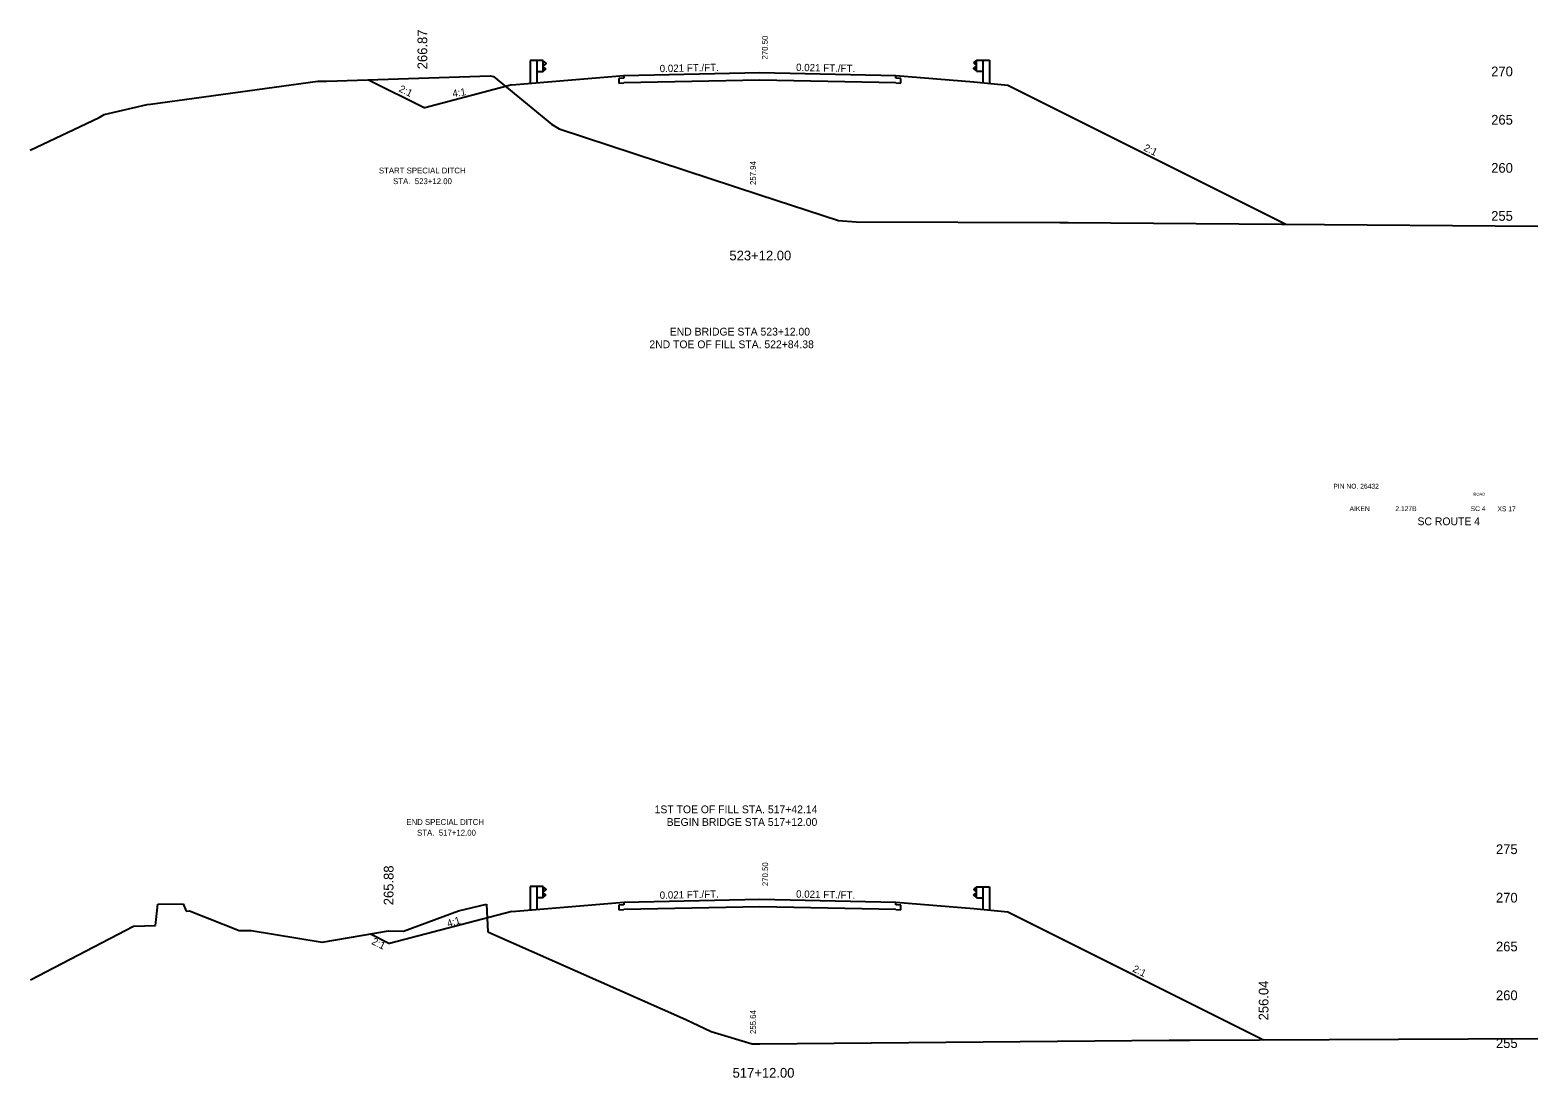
# Model space of a CAD drawing. Extents: x 883 to 1160, y 1002 to 4323.
# Drawn here: x 1005 to 1160, y 2882.1 to 2989.9 of the extents above; entities that cross this region are included whole.
import ezdxf

# ---------------------------------------------------------------- set-up
doc = ezdxf.new("R2010")
doc.units = 0
for name, color, linetype in [('Level 1', 7, 'Continuous'), ('Level 10', 7, 'Continuous'), ('Level 11', 7, 'Continuous'), ('Level 12', 7, 'Continuous'), ('Level 24', 7, 'Continuous'), ('Level 3', 7, 'Continuous'), ('Level 32', 7, 'Continuous'), ('Level 33', 7, 'Continuous'), ('Level 59', 7, 'Continuous'), ('Level 6', 7, 'Continuous'), ('Level 60', 7, 'Continuous'), ('Level 7', 7, 'Continuous')]:
    doc.layers.add(name, color=color, linetype=linetype)

msp = doc.modelspace()

# ---------------------------------------------------------------- linework, layer by layer
at = {"layer": 'Level 11'}
for p, q in [((1066, 2984.91), (1065.5, 2984.9)), ((1065.5, 2984.9), (1065.5, 2984.42)), ((1065.5, 2984.42), (1066, 2984.43)), ((1066, 2985.21), (1066, 2984.91)), ((1094, 2984.91), (1094, 2985.21)), ((1094.5, 2984.9), (1094, 2984.91)), ((1094, 2984.43), (1094.5, 2984.42)), ((1094.5, 2984.42), (1094.5, 2984.9)), ((1066, 2899.91), (1065.5, 2899.9)), ((1065.5, 2899.9), (1065.5, 2899.42)), ((1065.5, 2899.42), (1066, 2899.43)), ((1066, 2900.21), (1066, 2899.91)), ((1094, 2899.91), (1094, 2900.21)), ((1094.5, 2899.9), (1094, 2899.91)), ((1094, 2899.43), (1094.5, 2899.42)), ((1094.5, 2899.42), (1094.5, 2899.9))]:
    msp.add_line(p, q, dxfattribs=at)
at = {"layer": 'Level 12'}
for p, q in [((1080, 2984.72), (1066, 2984.43)), ((1094, 2984.43), (1080, 2984.72)), ((1080, 2899.72), (1066, 2899.43)), ((1094, 2899.43), (1080, 2899.72))]:
    msp.add_line(p, q, dxfattribs=at)
at = {"layer": 'Level 24'}
for p, q in [((1056.4, 2986.74), (1056.4, 2984.33)), ((1057.07, 2986.74), (1056.4, 2986.74)), ((1057.73, 2986.74), (1057.07, 2986.74)), ((1057.07, 2986.74), (1057.07, 2984.39)), ((1057.73, 2985.57), (1057.73, 2986.74)), ((1057.73, 2986.66), (1058, 2986.46)), ((1058, 2986.41), (1057.73, 2986.21)), ((1058, 2985.89), (1057.73, 2986.09)), ((1058, 2986.46), (1058, 2986.41)), ((1058, 2985.84), (1058, 2985.89)), ((1102.27, 2986.72), (1102, 2986.52)), ((1102, 2986.52), (1102, 2986.47)), ((1102, 2986.47), (1102.27, 2986.27)), ((1102, 2985.95), (1102.27, 2986.15)), ((1102, 2985.9), (1102, 2985.95)), ((1102.27, 2985.7), (1102, 2985.9)), ((1102.27, 2985.63), (1102.27, 2986.79)), ((1102.27, 2986.79), (1102.94, 2986.79)), ((1102.94, 2986.79), (1102.94, 2984.45)), ((1102.94, 2986.79), (1103.6, 2986.79)), ((1103.6, 2986.79), (1103.6, 2984.38)), ((1057.73, 2985.57), (1057.07, 2985.57)), ((1057.73, 2985.64), (1058, 2985.84)), ((1102.27, 2985.63), (1102.94, 2985.63)), ((1056.4, 2901.8), (1056.4, 2899.39)), ((1057.07, 2901.8), (1056.4, 2901.8)), ((1057.73, 2901.8), (1057.07, 2901.8)), ((1057.07, 2901.8), (1057.07, 2899.46)), ((1057.73, 2900.63), (1057.07, 2900.63)), ((1057.73, 2900.63), (1057.73, 2901.8)), ((1057.73, 2901.73), (1058, 2901.53)), ((1058, 2901.48), (1057.73, 2901.28)), ((1058, 2900.96), (1057.73, 2901.16)), ((1057.73, 2900.71), (1058, 2900.91)), ((1058, 2901.53), (1058, 2901.48)), ((1058, 2900.91), (1058, 2900.96)), ((1102.27, 2901.72), (1102, 2901.52)), ((1102, 2901.52), (1102, 2901.47)), ((1102, 2901.47), (1102.27, 2901.27)), ((1102, 2900.95), (1102.27, 2901.15)), ((1102, 2900.9), (1102, 2900.95)), ((1102.27, 2900.7), (1102, 2900.9)), ((1102.27, 2900.63), (1102.27, 2901.79)), ((1102.27, 2901.79), (1102.94, 2901.79)), ((1102.94, 2901.79), (1102.94, 2899.45)), ((1102.94, 2901.79), (1103.6, 2901.79)), ((1103.6, 2901.79), (1103.6, 2899.38)), ((1102.27, 2900.63), (1102.94, 2900.63))]:
    msp.add_line(p, q, dxfattribs=at)
at = {"layer": 'Level 59'}
for p, q in [((1066, 2985.21), (1080, 2985.5)), ((1080, 2985.5), (1094, 2985.21)), ((1066, 2900.21), (1080, 2900.5)), ((1080, 2900.5), (1094, 2900.21))]:
    msp.add_line(p, q, dxfattribs=at)
at = {"layer": 'Level 6'}
for p, q in [((1054.5, 2984.25), (1066, 2985.21)), ((1094, 2985.21), (1102, 2984.54)), ((1102, 2984.54), (1105.5, 2984.19)), ((1054.5, 2899.25), (1066, 2900.21)), ((1094, 2900.21), (1102, 2899.54)), ((1102, 2899.54), (1105.5, 2899.19))]:
    msp.add_line(p, q, dxfattribs=at)
at = {"layer": 'Level 60'}
for p, q in [((1017.33, 2982.26), (1034.54, 2984.62)), ((1034.54, 2984.62), (1035, 2984.63)), ((1035, 2984.63), (1035.46, 2984.62)), ((1035.46, 2984.62), (1052.27, 2985.15)), ((1052.27, 2985.15), (1052.63, 2985.1)), ((1052.63, 2985.1), (1058.57, 2980.18)), ((1012.58, 2981.2), (1017, 2982.21)), ((1017, 2982.21), (1017.33, 2982.26)), ((1004.97, 2977.53), (1012.08, 2980.89)), ((1012.08, 2980.89), (1012.58, 2981.2)), ((1058.57, 2980.18), (1059.36, 2979.73)), ((1059.36, 2979.73), (1080, 2972.94)), ((1080, 2972.94), (1088.09, 2970.28)), ((1088.09, 2970.28), (1089.92, 2970.14)), ((1089.92, 2970.14), (1110.86, 2970.07)), ((1110.86, 2970.07), (1111.7, 2970.07)), ((1111.7, 2970.07), (1160, 2969.72)), ((1017.85, 2897.81), (1018.09, 2900)), ((1018.09, 2900), (1020.7, 2900.04)), ((1020.7, 2900.04), (1021, 2899.28)), ((1021, 2899.28), (1021.37, 2899.3)), ((1021.37, 2899.3), (1026.47, 2897.29)), ((1043.37, 2897.23), (1049, 2899.3)), ((1049, 2899.3), (1051.88, 2899.98)), ((1051.88, 2899.98), (1052.04, 2897.16)), ((1005.02, 2892.21), (1015.59, 2897.74)), ((1015.59, 2897.74), (1017.85, 2897.81)), ((1026.47, 2897.29), (1027.71, 2897.27)), ((1027.71, 2897.27), (1035, 2896.08)), ((1035, 2896.08), (1041.83, 2897.26)), ((1041.83, 2897.26), (1043.37, 2897.23)), ((1052.04, 2897.16), (1072.4, 2888.12)), ((1072.4, 2888.12), (1075.01, 2886.89)), ((1075.01, 2886.89), (1079.21, 2885.63)), ((1079.21, 2885.63), (1080, 2885.64)), ((1080, 2885.64), (1122.09, 2886.02)), ((1122.09, 2886.02), (1122.73, 2886.02)), ((1122.73, 2886.02), (1124.2, 2886)), ((1124.2, 2886), (1160, 2886.19))]:
    msp.add_line(p, q, dxfattribs=at)
at = {"layer": 'Level 7'}
for p, q in [((1039.75, 2984.75), (1045.54, 2981.86)), ((1054.5, 2984.25), (1045.54, 2981.86)), ((1105.5, 2984.19), (1134.07, 2969.91)), ((1054.5, 2899.25), (1041.91, 2895.96)), ((1105.5, 2899.19), (1131.8, 2886.04)), ((1039.96, 2896.94), (1041.91, 2895.96))]:
    msp.add_line(p, q, dxfattribs=at)

# ---------------------------------------------------------------- texts
at = {"layer": 'Level 1'}
for s, height, p in [('523+12.00', 1, (1076.87, 2966.19)), ('END BRIDGE STA 523+12.00', 0.8, (1070.74, 2958.46)), ('2ND TOE OF FILL STA. 522+84.38', 0.8, (1068.64, 2957.16)), ('PIN NO. 26432', 0.5, (1138.97, 2942.72)), ('AIKEN', 0.5, (1140.64, 2940.41)), (' 2.127B', 0.5, (1145.15, 2940.41)), ('SC ROUTE 4', 0.8, (1147.63, 2938.96)), ('SC 4', 0.5, (1153.09, 2940.41)), ('XS 17', 0.5, (1155.85, 2940.39)), ('1ST TOE OF FILL STA. 517+42.14', 0.8, (1069.18, 2909.34)), ('BEGIN BRIDGE STA 517+12.00', 0.8, (1070.42, 2908.04)), ('517+12.00', 1, (1077.2, 2882.15))]:
    msp.add_text(s, height=height, dxfattribs=at).set_placement(p)
at = {"layer": 'Level 10'}
for s, p in [('257.94', (1079.6, 2973.94)), ('255.64', (1079.6, 2886.64))]:
    msp.add_text(s, height=0.6, rotation=90, dxfattribs=at).set_placement(p)
at = {"layer": 'Level 3'}
for s, height, p in [(' 270', 1, (1154.83, 2985.12)), (' 265', 1, (1154.83, 2980.15)), (' 260', 1, (1154.83, 2975.2)), (' 255', 1, (1154.83, 2970.26)), ('ROAD', 0.3, (1153.38, 2941.99)), (' 275', 1, (1155.32, 2905.14)), (' 270', 1, (1155.32, 2900.16)), (' 265', 1, (1155.32, 2895.14)), (' 260', 1, (1155.32, 2890.12)), (' 255', 1, (1155.32, 2885.2))]:
    msp.add_text(s, height=height, dxfattribs=at).set_placement(p)
at = {"layer": 'Level 32'}
for s, rotation, p in [('0.021 FT./FT.', 1.1916, (1069.71, 2985.54)), ('0.021 FT./FT.', 358.8084, (1083.72, 2985.67)), ('2:1', 333.435, (1042.81, 2983.59)), ('4:1', 9.4623, (1048.45, 2982.96)), ('2:1', 333.435, (1119.39, 2977.53)), ('0.021 FT./FT.', 1.1916, (1069.71, 2900.54)), ('0.021 FT./FT.', 358.8084, (1083.72, 2900.67)), ('4:1', 17.8076, (1047.96, 2897.61)), ('2:1', 333.435, (1040.01, 2895.92)), ('2:1', 333.435, (1118.25, 2893.1))]:
    msp.add_text(s, height=0.75, rotation=rotation, dxfattribs=at).set_placement(p)
for s, p in [('START SPECIAL DITCH', (1040.83, 2975.13)), ('STA.  523+12.00', (1042.29, 2974.03)), ('END SPECIAL DITCH', (1043.65, 2908.14)), ('STA.  517+12.00', (1044.76, 2907.04))]:
    msp.add_text(s, height=0.6, dxfattribs=at).set_placement(p)
at = {"layer": 'Level 33'}
for s, p in [('266.87', (1045.8, 2985.84)), ('265.88', (1042.33, 2899.88)), ('256.04', (1132.3, 2888.04))]:
    msp.add_text(s, height=1, rotation=90, dxfattribs=at).set_placement(p)
at = {"layer": 'Level 59'}
for p in [(1080.82, 2986.62), (1080.85, 2901.62)]:
    msp.add_text(' 270.50', height=0.6, rotation=90, dxfattribs=at).set_placement(p)

doc.saveas('drawing.dxf')
